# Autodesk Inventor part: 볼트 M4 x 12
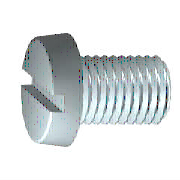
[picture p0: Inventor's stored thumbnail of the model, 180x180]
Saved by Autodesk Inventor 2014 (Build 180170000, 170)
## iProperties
Created: 2012-02
Part Number: 볼트 M4 x 12
Material: 강철, 연강
Description: 6각머리 태핑 나사
Document SubType Name: Modeling
Standard: KS B 1021
Designer: mduedu
Standards Organization: KS
Language: ko-KR
Size Designation: A  M 4 x 12
Categories: <MemberInstance><Categories><Category DisplayName="조임쇠" InternalName="e4da775c-781d-43d5-af7c-5136215cf5a6" Mnemonic="FSTN"><Category DisplayName="볼트" InternalN
Density: 1 g/cm^3
Appearance: Steel
IsCustomPart: 0
Author: mduedu
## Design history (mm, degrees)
body "Solid1"
revolve "본체" stored, may be unused: angle "d8" = 90 deg
sketch "스케치2"
  geometry: L1 (0, 0)-(0, 3.273) reference; L2 (-3.5, 0.6)-(3.5, 0.6); L3 (3.5, 0.6)-(3.5, -0.6); L4 (3.5, -0.6)-(-3.5, -0.6); L5 (-3.5, -0.6)-(-3.5, 0.6); L6 (-3.5, 0)-(3.5, 0); L7 (0, 0.6)-(0, -0.6); C1 r 3.5 at (0, 0) reference; 1 further point
  constraints: 12 end point, 5 midpoint, 2 parallel, 1 collinear, 1 horizontal, 1 perpendicular
  dimensions: "d11" = 1.2 distance of L4.end L2.start (= SBR); "d12" = 7 distance of L2.start L2.end (= KOD)
fillet "모깎기1" dims "d14" = 0.2 (= RR)
extrude "슬롯" cut sketch "스케치2" distance "d19" = 1.1 (= STI); taper "d20" = 0 deg
feature "스레드" dims "d15" = 10.6 (= GEL), "d16" = 0
chamfer "모따기1" distance "d17" = 0.42941 (= -0.5 x SPD + 0.5 x GD); stored, may be unused: second distance "d18" = 0.42952 (computed from GUL), angle "d36" = 45 deg
workplane "Work Plane1"
sketch "스케치1"
  geometry: L1 (-2.6, 0)-(12, 0); L2 (12, 0)-(12, 2); L3 (12, 2)-(1.4, 2); L4 (1.4, 2)-(0.97, 1.785); L5 (0.97, 1.785)-(0, 1.785); L6 (0, 1.785)-(0, 3.5); L7 (-5.52, 0)-(14.92, 0) reference; L8 (0, -0.7)-(0, 4.2) reference; L9 (-2.6, 0)-(-2.6, 3.273); L10 (0, 3.5)-(-2.6, 3.273); L11 (1.4, 2)-(0, 2)
  constraints: 18 end point, 4 parallel, 2 collinear, 2 perpendicular, 1 horizontal, 1 point on line
  dimensions: "d0" = 12 distance between parallel lines of L2 L6 (= NLG); "d1" = 10.6 distance from line of L3.end L2 (= GEL); "d2" = 0.42952 horizontal distance of L4.end L3.end (computed from GAL); "d3" = 2.6 distance from line of L1.start L6 (= KOH); "d4" = 4 diameter of L3 L1 (= GD); "d5" = 3.5705 diameter of L5 L1 (= BDM); "d9" = 7 diameter of L6.end L1 (= KOD); "d10" = 5 deg angle of L10 L1 (= KEWI)
other parameters: "GD" = 4 (= NND) [user parameter; used in 2 equation terms], "NLG" = 12 [user parameter; used in 1 equation term], "GEL" = 10.6 [user parameter; used in 2 equation terms], "KOD" = 7 [user parameter; used in 2 equation terms], "KOH" = 2.6 [user parameter; used in 1 equation term], "GAL" = 0.42941 (= 0.61345 x PTC) [user parameter; used in 1 equation term], "SPD" = 3.14117 (= NND - 1.2269 x PTC) [user parameter; used in 1 equation term], "BDM" = 3.5705 [user parameter; used in 1 equation term], "GUL" = 0.42941 (= 0.61345 x PTC) [user parameter; used in 1 equation term], "RR" = 0.2 [user parameter; used in 1 equation term], "d7" = 0, "SBR" = 1.2 [user parameter; used in 1 equation term], "STI" = 1.1 [user parameter; used in 1 equation term], "KEWI" = 5 deg [user parameter; used in 1 equation term], "d37" = 0, "d39" = 0, "PTC" = 0.7 [user parameter; used in 5 equation terms], "THREADDIA" = 4 [user parameter; used in 1 equation term], "TOA" = 30 deg [user parameter], "TPU" = 14.28571 (computed from PTC) [user parameter], "NND" = 4 [user parameter; used in 2 equation terms], "GD1" = 3.14117 (= THREADDIA - 1.2269 x PTC) [user parameter]
